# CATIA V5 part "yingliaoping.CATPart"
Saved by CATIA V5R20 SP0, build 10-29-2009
Part number: yingliaoping
Material "Summer sky"
Material "DS star": density 1000 kg/m3
Bounding box of the stored display mesh (mm): x -25 to 26, y -25 to 25, z 0 to 110
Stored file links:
  D:\3D工程制图\180512310 付紫桐\yingliaoping.CATPart
  D:\CATIAR20\win_b64\startup\materials\Catalog.CATMaterial
  D:\CATIAR20\win_b64\startup\materials\fence_3.jpg
  D:\CATIAR20\win_b64\startup\materials\canvas.jpg
  D:\CATIAR20\win_b64\startup\materials\brown_fiber.jpg
  D:\CATIAR20\win_b64\startup\materials\marble_paving.jpg
  D:\CATIAR20\win_b64\startup\materials\old_tile.jpg
  D:\CATIAR20\win_b64\startup\materials\wall_of_bricks.jpg
  D:\CATIAR20\win_b64\startup\materials\roughcast.jpg
  D:\CATIAR20\win_b64\startup\materials\grid.png
  D:\CATIAR20\win_b64\startup\materials\blue_env_512x512.jpg
  D:\CATIAR20\win_b64\startup\materials\DS_star.jpg
  D:\CATIAR20\win_b64\startup\materials\chessboard.jpg
  D:\CATIAR20\win_b64\startup\materials\sunset.jpg
  D:\CATIAR20\win_b64\startup\materials\summer_sky.jpg
  D:\CATIAR20\win_b64\startup\materials\no_skid.jpg
  D:\CATIAR20\win_b64\startup\materials\blue_onyx.jpg
  D:\CATIAR20\win_b64\startup\materials\pinetree.jpg
  D:\CATIAR20\win_b64\startup\materials\wire.png
  D:\CATIAR20\win_b64\startup\materials\losange_fabric.jpg
  D:\CATIAR20\win_b64\startup\materials\honeycomb.jpg
  D:\CATIAR20\win_b64\startup\materials\canvas.png
  D:\CATIAR20\win_b64\startup\materials\marble.jpg
  D:\CATIAR20\win_b64\startup\materials\pink_marble.jpg
  D:\CATIAR20\win_b64\startup\materials\sand.jpg
  D:\CATIAR20\win_b64\startup\materials\grate.jpg
  D:\CATIAR20\win_b64\startup\materials\raw_polystyren.jpg
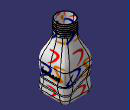
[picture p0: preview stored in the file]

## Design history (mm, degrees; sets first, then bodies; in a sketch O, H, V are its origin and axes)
Set1
  Sketch1 on xy-plane, origin (0, 0, 0), H (1, 0, 0), V (0, 1, 0)
    line L1 (25, 25) -> (25, -25)
    line L2 (25, -25) -> (-25, -25)
    line L3 (-25, -25) -> (-25, 25)
    line L4 (-25, 25) -> (25, 25)
    length L4 = 50
    length L1 = 50
    vertical: L1 V, L3 V
    horizontal: L2 H, L4 H
    equidistance: L1 L3 O, L2 L4 O
  Sketch2 on face of Pad1 from Sketch1.L2, origin (0, -25, 0), H (1, 0, 0), V (0, 0, 1)
    spline S1 through (-40.13, 17.5064) (-4.5865, 26.557) (17.4166, 15.9725) (37.4194, 24.256)
  Extrude1: Element1 Sketch2, Lim1 60, Lim2 60
  MultiSel1: CommonCtxFeats ({extract ExtractElem face of Pad1 from Sketch1.L2}; {extract ExtractElem face of Fillet1}; {extract ExtractElem face of Pad1 from Sketch1.L1}; {extract ExtractElem face of Fillet1}; {extract ExtractElem face of Pad1 from Sketch1.L4}; {extract ExtractElem face of Fillet1}; {extract ExtractElem face of Pad1 from Sketch1.L3}; {extract ExtractElem face of Fillet1}; {join Elements ({intersect ToIntersect1 {extract ExtractElem face of Pad1 from Sketch1.L2}, ToIntersect2 Extrude1}; {intersect ToIntersect1 {extract ExtractElem face of Fillet1}, ToIntersect2 Extrude1}; {intersect ToIntersect1 {extract ExtractElem face of Pad1 from Sketch1.L1}, ToIntersect2 Extrude1}; {intersect ToIntersect1 {extract ExtractElem face of Pad1 from Sketch1.L4}, ToIntersect2 Extrude1}; {intersect ToIntersect1 {extract ExtractElem face of Fillet1}, ToIntersect2 Extrude1}; {intersect ToIntersect1 {extract ExtractElem face of Fillet1}, ToIntersect2 Extrude1}; {intersect ToIntersect1 {extract ExtractElem face of Pad1 from Sketch1.L3}, ToIntersect2 Extrude1}; {intersect ToIntersect1 {extract ExtractElem face of Fillet1}, ToIntersect2 Extrude1})})
  Sketch3 on face of Pad1 from Sketch1.L2, origin (0, -25, 0), H (1, 0, 0), V (0, 0, 1)
    spline S1 through (-31.3579, 34.1236) (-14.7105, 40.4955) (13.6792, 27.8998) (28.8403, 27.8998)
  Extrude2: Element1 Sketch3, Lim1 60, Lim2 60
  MultiSel2: CommonCtxFeats ({extract ExtractElem face of Fillet1}; {extract ExtractElem face of Pad1 from Sketch1.L1}; {extract ExtractElem face of Fillet1}; {extract ExtractElem face of Pad1 from Sketch1.L4}; {extract ExtractElem face of Fillet1}; {extract ExtractElem face of Pad1 from Sketch1.L3}; {extract ExtractElem face of Fillet1}; {extract ExtractElem face of Pad1 from Sketch1.L2}; {join Elements ({intersect ToIntersect1 {extract ExtractElem face of Fillet1}, ToIntersect2 Extrude2}; {intersect ToIntersect1 {extract ExtractElem face of Pad1 from Sketch1.L1}, ToIntersect2 Extrude2}; {intersect ToIntersect1 {extract ExtractElem face of Fillet1}, ToIntersect2 Extrude2}; {intersect ToIntersect1 {extract ExtractElem face of Pad1 from Sketch1.L4}, ToIntersect2 Extrude2}; {intersect ToIntersect1 {extract ExtractElem face of Fillet1}, ToIntersect2 Extrude2}; {intersect ToIntersect1 {extract ExtractElem face of Pad1 from Sketch1.L3}, ToIntersect2 Extrude2}; {intersect ToIntersect1 {extract ExtractElem face of Fillet1}, ToIntersect2 Extrude2}; {intersect ToIntersect1 {extract ExtractElem face of Pad1 from Sketch1.L2}, ToIntersect2 Extrude2})})
  Plane1: type Normal, Curve {intersect ToIntersect1 {extract ExtractElem face of Pad1 from Sketch1.L4}, ToIntersect2 Extrude2}, RefPoint vertex of MultiSel2
  Sketch4 on Plane1, origin (-17.4023, 0, 0.6186), H (0, 1, 0), V (0.0355, 0, 0.9994)
    circle A1 centre (25.3111, 40.1619) radius 1
    radius A1 = 1
  Plane2: type Normal, Curve {intersect ToIntersect1 {join Elements ({intersect ToIntersect2 Extrude1}; {intersect ToIntersect2 Extrude1}; {intersect ToIntersect2 Extrude1}; {intersect ToIntersect2 Extrude1}; {intersect ToIntersect2 Extrude1}; {intersect ToIntersect2 Extrude1}; {intersect ToIntersect2 Extrude1}; {intersect ToIntersect2 Extrude1})}, ToIntersect2 Extrude1}, RefPoint vertex of MultiSel1
  Sketch5 on Plane2, origin (-17.7485, 0, 3.598), H (0, -1, 0), V (0.1987, 0, 0.9801)
    circle A1 centre (-24.9885, 25.9108) radius 1
    radius A1 = 1
Body1 (main body), material "DS star"
  Pad1: profile Sketch1, direction (0, 0, 1), length 50
  Fillet1: on edge [face of Pad1 from Sketch1.L4 | face of Pad1 from Sketch1.L1]; edge [face of Pad1 from Sketch1.L3 | face of Pad1 from Sketch1.L4]; edge [face of Pad1 from Sketch1.L1 | face of Pad1 from Sketch1.L2]; edge [face of Pad1 from Sketch1.L2 | face of Pad1 from Sketch1.L3]
  Fillet2: radius 8, on edge [start face of Pad1 | face of Pad1 from Sketch1.L1]
  Plane3: type Offset, RefPlane end face of Pad1, Offset 40, reversed
  Sketch6 on Plane3, origin (0, 0, 90), H (1, 0, 0), V (0, -1, 0)
    circle A1 centre (0, 0) radius 15
    radius A1 = 15
  Pad2: profile Sketch6, direction (0, 0, 1), length 20
  Sketch7 on end face of Pad1, origin (0, 0, 50), H (1, 0, 0), V (0, 1, 0)
    point P1 (25, 0)
    distance P1 O = 25
    coincidence: P1 H
  Sketch8 on start face of Pad2, origin (0, 0, 90), H (1, 0, 0), V (0, -1, 0)
    point P1 (15, 0)
    distance P1 O = 15
    coincidence: P1 H
  Loft1: solid, Sections ({boundary Boundary {extract ExtractElem end face of Pad1}}; {boundary Boundary {extract ExtractElem start face of Pad2}}), StartFace end face of Pad1, EndFace start face of Pad2
  Slot1: profile Sketch4, centre curve {intersect ToIntersect1 {join}, ToIntersect2 Extrude2}
  Slot2: profile Sketch5, centre curve {intersect ToIntersect1 {join}, ToIntersect2 Extrude1}
  Shell1: IntOffset 1, Face end face of Pad2, ExtOffset 0
  Plane4: type Offset, RefPlane {extract ExtractElem start face of Pad2}, Offset 2
  Sketch9 on Plane4, origin (0, 0, 92), H (1, 0, 0), V (0, 1, 0)
    point P1 (15, 0)
    distance P1 O = 15
    coincidence: P1 H
  Helix1: Direction Z axis, RefPoint Sketch9, Pitch 3, Height 16, TaperAngle 0
  Line1: type PtDir, RefPoint Sketch9, Direction (1, 0, 0), Start 0, End 5
  Line2: type PtDir, RefPoint vertex of Helix1, Direction (0, 1, 0), Start 0, End 5
  Point1: type OnCurve, Support Helix1, Length 6.943
  Point2: type OnCurve, Support Helix1, RefPoint vertex of Helix1, Length -5.555
  Connect1: Curve1 Line2, Point1 vertex of Line2, Tension1 1, Curve2 Helix1, Point2 Point2, Tension2 1
  Connect2: Curve1 Line1, Point1 vertex of Line1, Tension1 1, Curve2 Connect1, Point2 Point1, Tension2 1
  Plane5: type Normal, Curve Connect2, RefPoint vertex of Connect2
  Sketch10 on Plane5, origin (10, 0, 0), H (0, 1, 0), V (0, 0, 1)
    circle A1 centre (0, 92.0244) radius 0.5
    point P1 (0, 92.0244)
    radius A1 = 0.5
    coincidence: P1 V
  Rib1: profile Sketch10, centre curve Connect2, thin wall 10
  Body2
    Sketch11 on Plane4, origin (0, 0, 92), H (1, 0, 0), V (0, 1, 0)
      circle A1 centre (0, 0) radius 14
      radius A1 = 14
    Pad3: profile Sketch11, direction (0, 0, -1), length 20, mirrored extent
  Remove1: tool Body2
Body3, material "Summer sky"
  Sketch12 on face of Pad1 from Sketch1.L1, origin (25, 0, 0), H (0, 1, 0), V (0, 0, 1)
    polyline C1
    polyline C2
    polyline C3
    polyline C4
    polyline C5
    polyline C6
    polyline C7
    polyline C8
    polyline C9
    polyline C10
    polyline C11
  Pocket1: profile Sketch12, direction (1, 0, 0), length 1
  Sketch13 on Plane4, origin (0, 0, 92), H (1, 0, 0), V (0, 1, 0)
    circle A1 centre (0, 0) radius 15
    radius A1 = 15
  Pad4: profile Sketch13, direction (0, 0, 1), length 20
